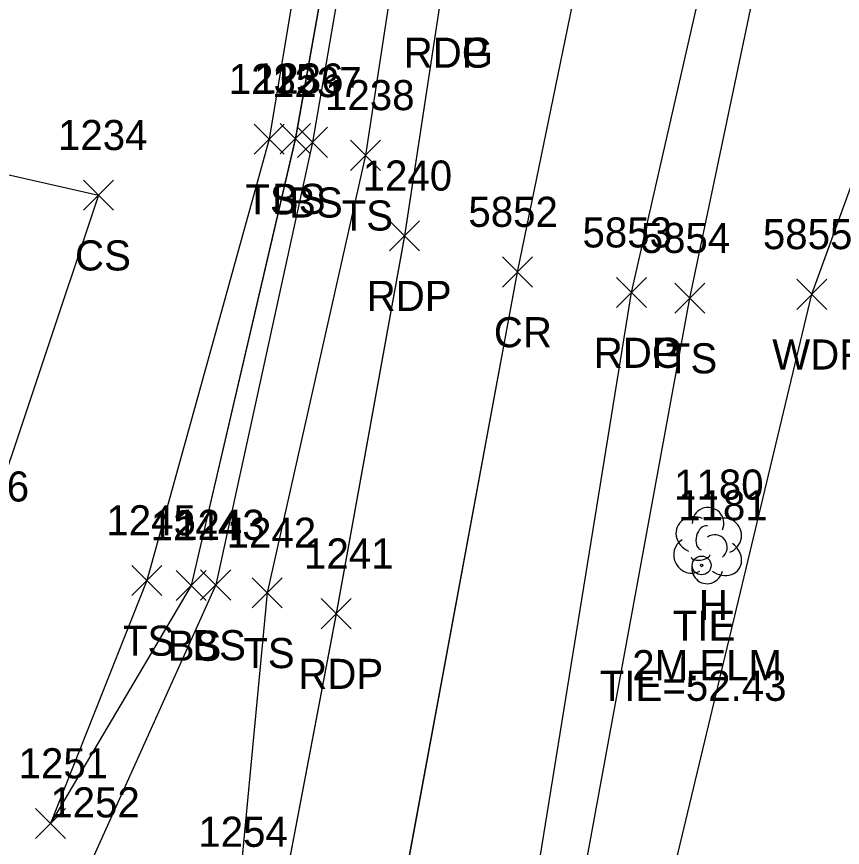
# Model space of a CAD drawing. Extents: x 1554668 to 1563881, y 831386 to 834374.
# Drawn here: x 1561833.7 to 1561888.6, y 833679 to 833734.2 of the extents above; entities that cross this region are included whole.
import ezdxf

# ---------------------------------------------------------------- set-up
doc = ezdxf.new("R2010")
doc.units = 0
for name, color, linetype in [('C_A', 7, 'Continuous'), ('C_C', 7, 'Continuous'), ('C_I', 7, 'Continuous'), ('CBP', 7, 'Continuous'), ('L_A', 7, 'Continuous'), ('L_C', 7, 'Continuous'), ('L_I', 7, 'Continuous'), ('L_TIC', 7, 'Continuous'), ('LAWA', 7, 'Continuous'), ('LELB', 7, 'Continuous'), ('LTD', 7, 'Continuous'), ('P_A', 7, 'Continuous'), ('P_I', 7, 'Continuous'), ('P_TIC', 7, 'Continuous'), ('PET', 7, 'Continuous'), ('PEU', 7, 'Continuous'), ('PRC', 7, 'Continuous')]:
    doc.layers.add(name, color=color, linetype=linetype)

msp = doc.modelspace()

# ---------------------------------------------------------------- linework, layer by layer
at = {"layer": 'CBP'}
for radius in [0.625, 0.0833]:
    msp.add_circle((1561879.207, 833697.748), radius, dxfattribs=at)
at = {"layer": 'L_TIC'}
for points in [[(1561849.467, 833725.074), (1561851.467, 833727.074)], [(1561851.467, 833725.074), (1561849.467, 833727.074)], [(1561851.199, 833725.106), (1561853.199, 833727.106)], [(1561853.199, 833725.106), (1561851.199, 833727.106)], [(1561852.344, 833724.866), (1561854.344, 833726.866)], [(1561854.344, 833724.866), (1561852.344, 833726.866)], [(1561855.867, 833724.001), (1561857.867, 833726.001)], [(1561857.867, 833724.001), (1561855.867, 833726.001)], [(1561838.114, 833721.348), (1561840.114, 833723.348)], [(1561840.114, 833721.348), (1561838.114, 833723.348)], [(1561877.419, 833714.511), (1561879.419, 833716.511)], [(1561879.419, 833714.511), (1561877.419, 833716.511)], [(1561885.539, 833714.765), (1561887.539, 833716.765)], [(1561887.539, 833714.765), (1561885.539, 833716.765)], [(1561841.33, 833695.748), (1561843.33, 833697.748)], [(1561843.33, 833695.748), (1561841.33, 833697.748)], [(1561844.274, 833695.41), (1561846.274, 833697.41)], [(1561846.274, 833695.41), (1561844.274, 833697.41)], [(1561845.906, 833695.447), (1561847.906, 833697.447)], [(1561847.906, 833695.447), (1561845.906, 833697.447)], [(1561849.329, 833694.923), (1561851.329, 833696.923)], [(1561851.329, 833694.923), (1561849.329, 833696.923)], [(1561834.929, 833679.601), (1561836.929, 833681.601)], [(1561836.929, 833679.601), (1561834.929, 833681.601)], [(1561834.929, 833679.601), (1561836.929, 833681.601)], [(1561836.929, 833679.601), (1561834.929, 833681.601)]]:
    msp.add_lwpolyline(points, dxfattribs=at)
at = {"layer": 'LAWA'}
for points in [[(1561868.017, 833554.593), (1561853.324, 833557.227), (1561862.973, 833614.369), (1561874.798, 833666.739), (1561886.539, 833715.765), (1561895.993, 833741.804), (1561893.776, 833756.696), (1561896.793, 833771.816), (1561900.446, 833801.465), (1561911.698, 833843.705), (1561917.941, 833890.876), (1561919.948, 833896.933), (1561931.794, 833916.188)], [(1561868.017, 833554.587), (1561853.326, 833557.225), (1561862.972, 833614.373), (1561874.796, 833666.738), (1561886.54, 833715.766), (1561895.995, 833741.807), (1561893.775, 833756.693), (1561896.794, 833771.816), (1561900.447, 833801.462), (1561911.703, 833843.707), (1561917.942, 833890.875), (1561919.949, 833896.931), (1561931.795, 833916.187)], [(1561868.017, 833554.587), (1561853.326, 833557.225), (1561862.972, 833614.373), (1561874.796, 833666.738), (1561886.54, 833715.766), (1561895.995, 833741.807), (1561893.775, 833756.693), (1561896.794, 833771.816), (1561900.447, 833801.462), (1561911.703, 833843.707), (1561917.942, 833890.875), (1561919.949, 833896.931), (1561931.795, 833916.187)], [(1561868.017, 833554.587), (1561853.326, 833557.225), (1561862.972, 833614.373), (1561874.796, 833666.738), (1561886.54, 833715.766), (1561895.995, 833741.807), (1561893.775, 833756.693), (1561896.794, 833771.816), (1561900.447, 833801.462), (1561911.703, 833843.707), (1561917.942, 833890.875), (1561919.949, 833896.931), (1561931.795, 833916.187)]]:
    msp.add_lwpolyline(points, dxfattribs=at)
at = {"layer": 'LELB'}
for points in [[(1561812.716, 833374.079), (1561818.656, 833401.248), (1561824.645, 833433.945), (1561832.252, 833470.48), (1561836.457, 833492.444), (1561840.257, 833509.466), (1561848.879, 833557.929), (1561859.972, 833614.877), (1561869.557, 833667.191), (1561878.418, 833715.509), (1561890.593, 833773.388), (1561895.718, 833803.087)], [(1561812.716, 833374.079), (1561818.656, 833401.248), (1561824.645, 833433.945), (1561832.252, 833470.48), (1561836.457, 833492.444), (1561840.257, 833509.466), (1561848.879, 833557.929), (1561859.972, 833614.877), (1561869.557, 833667.191), (1561878.418, 833715.509), (1561890.593, 833773.388), (1561895.718, 833803.087)], [(1561812.716, 833374.079), (1561818.656, 833401.248), (1561824.645, 833433.945), (1561832.252, 833470.48), (1561836.457, 833492.444), (1561840.257, 833509.466), (1561848.879, 833557.929), (1561859.972, 833614.877), (1561869.557, 833667.191), (1561878.418, 833715.509), (1561890.593, 833773.388), (1561895.718, 833803.087)], [(1561812.717, 833374.086), (1561818.657, 833401.257), (1561824.644, 833433.948), (1561832.251, 833470.485), (1561836.455, 833492.446), (1561840.257, 833509.472), (1561848.879, 833557.936), (1561859.973, 833614.873), (1561869.554, 833667.19), (1561878.419, 833715.511), (1561890.594, 833773.393), (1561895.717, 833803.083)], [(1561806.296, 833788.777), (1561837.712, 833773.958), (1561847.53, 833767.441), (1561857.265, 833760.518), (1561858.213, 833759.926), (1561859.161, 833759.715), (1561853.344, 833725.866), (1561846.906, 833696.447), (1561838.604, 833678.002)], [(1561806.297, 833788.773), (1561837.712, 833773.96), (1561847.53, 833767.436), (1561857.266, 833760.521), (1561858.213, 833759.923), (1561859.161, 833759.712), (1561853.344, 833725.864), (1561846.906, 833696.45), (1561838.605, 833677.998)], [(1561806.297, 833788.773), (1561837.712, 833773.96), (1561847.53, 833767.436), (1561857.266, 833760.521), (1561858.213, 833759.923), (1561859.161, 833759.712), (1561853.344, 833725.864), (1561846.906, 833696.45), (1561838.605, 833677.998)], [(1561806.297, 833788.773), (1561837.712, 833773.96), (1561847.53, 833767.436), (1561857.266, 833760.521), (1561858.213, 833759.923), (1561859.161, 833759.712), (1561853.344, 833725.864), (1561846.906, 833696.45), (1561838.605, 833677.998)], [(1561848.403, 833772.22), (1561859.088, 833762.967), (1561862.218, 833760.08), (1561856.867, 833725.001), (1561850.329, 833695.923), (1561848.444, 833676.048), (1561846.147, 833662.128), (1561840.876, 833636.676), (1561837.465, 833618.453), (1561834.406, 833616.246), (1561820.201, 833618.031), (1561806.977, 833621.804), (1561796.8, 833625.141), (1561796.213, 833627.925), (1561779.239, 833633.983)], [(1561848.403, 833772.219), (1561859.088, 833762.966), (1561862.218, 833760.077), (1561856.867, 833725.003), (1561850.329, 833695.921), (1561848.444, 833676.044), (1561846.147, 833662.13), (1561840.875, 833636.672), (1561837.466, 833618.455), (1561834.407, 833616.245), (1561820.203, 833618.032), (1561806.976, 833621.803), (1561796.804, 833625.143), (1561796.218, 833627.927), (1561779.24, 833633.983)], [(1561848.403, 833772.219), (1561859.088, 833762.966), (1561862.218, 833760.077), (1561856.867, 833725.003), (1561850.329, 833695.921), (1561848.444, 833676.044), (1561846.147, 833662.13), (1561840.875, 833636.672), (1561837.466, 833618.455), (1561834.407, 833616.245), (1561820.203, 833618.032), (1561806.976, 833621.803), (1561796.804, 833625.143), (1561796.218, 833627.927), (1561779.24, 833633.983)], [(1561848.403, 833772.219), (1561859.088, 833762.966), (1561862.218, 833760.077), (1561856.867, 833725.003), (1561850.329, 833695.921), (1561848.444, 833676.044), (1561846.147, 833662.13), (1561840.875, 833636.672), (1561837.466, 833618.455), (1561834.407, 833616.245), (1561820.203, 833618.032), (1561806.976, 833621.803), (1561796.804, 833625.143), (1561796.218, 833627.927), (1561779.24, 833633.983)], [(1561857.266, 833760.521), (1561853.903, 833746.709), (1561850.468, 833726.074), (1561842.33, 833696.752), (1561835.928, 833680.605)], [(1561857.266, 833760.521), (1561853.903, 833746.709), (1561850.468, 833726.074), (1561842.33, 833696.752), (1561835.928, 833680.605)], [(1561857.266, 833760.521), (1561853.903, 833746.709), (1561850.468, 833726.074), (1561842.33, 833696.752), (1561835.928, 833680.605)], [(1561857.265, 833760.518), (1561853.903, 833746.712), (1561850.467, 833726.074), (1561842.33, 833696.748), (1561835.929, 833680.601)], [(1561858.213, 833759.923), (1561852.2, 833726.109), (1561845.275, 833696.408), (1561835.928, 833680.605)], [(1561858.213, 833759.923), (1561852.2, 833726.109), (1561845.275, 833696.408), (1561835.928, 833680.605)], [(1561858.213, 833759.923), (1561852.2, 833726.109), (1561845.275, 833696.408), (1561835.928, 833680.605)], [(1561858.213, 833759.926), (1561852.199, 833726.106), (1561845.274, 833696.41), (1561835.929, 833680.601)], [(1561803.868, 833733.614), (1561825.939, 833725.332), (1561839.114, 833722.348), (1561831.301, 833698.995), (1561820.896, 833675.994)], [(1561803.87, 833733.611), (1561825.939, 833725.334), (1561839.115, 833722.351), (1561831.302, 833698.995), (1561820.898, 833675.993)], [(1561803.87, 833733.611), (1561825.939, 833725.334), (1561839.115, 833722.351), (1561831.302, 833698.995), (1561820.898, 833675.993)], [(1561803.87, 833733.611), (1561825.939, 833725.334), (1561839.115, 833722.351), (1561831.302, 833698.995), (1561820.898, 833675.993)]]:
    msp.add_lwpolyline(points, dxfattribs=at)
at = {"layer": 'LTD'}
msp.add_line((1561879.588, 833699.12), (1561879.588, 833699.12), dxfattribs=at)
msp.add_line((1561879.588, 833699.12), (1561879.588, 833699.12), dxfattribs=at)
msp.add_arc((1561879.635, 833700.554), 1.047, 335.5272, 180.9563, dxfattribs=at)
for centre, major_axis, ratio, start_param, end_param in [((1561878.797, 833699.786), (1.21, -0.512), 0.895232, 1.570796, 4.712389), ((1561880.63, 833699.703), (-1.141, -0.483), 0.949671, 1.570796, 4.712389), ((1561879.38, 833699.578), (-0.208, -0.792), 0.645439, 3.141593, 6.283185), ((1561878.505, 833698.411), (0.584, -1.042), 0.959034, 3.141593, 6.283185), ((1561880.088, 833698.953), (-0.5, 0.667), 0.989748, 3.141593, 6.283185), ((1561880.588, 833698.287), (-1.09, 0.792), 0.841452, 1.570796, 4.712389), ((1561879.13, 833698.37), (-0.625, -0.083), 0.423636, 0, 3.141593), ((1561879.589, 833697.62), (0.265, 1.061), 0.942809, 1.570796, 4.712389)]:
    msp.add_ellipse(centre, major_axis=major_axis, ratio=ratio, start_param=start_param, end_param=end_param, dxfattribs=at)
at = {"layer": 'P_TIC'}
for points in [[(1561858.453, 833718.656), (1561860.453, 833720.656)], [(1561860.453, 833718.656), (1561858.453, 833720.656)], [(1561865.962, 833716.246), (1561867.962, 833718.246)], [(1561867.962, 833716.246), (1561865.962, 833718.246)], [(1561873.547, 833714.877), (1561875.547, 833716.877)], [(1561875.547, 833714.877), (1561873.547, 833716.877)], [(1561873.547, 833714.877), (1561875.547, 833716.877)], [(1561875.547, 833714.877), (1561873.547, 833716.877)], [(1561853.907, 833693.541), (1561855.907, 833695.541)], [(1561855.907, 833693.541), (1561853.907, 833695.541)]]:
    msp.add_lwpolyline(points, dxfattribs=at)
at = {"layer": 'PET'}
for points in [[(1561861.913, 833735.821), (1561859.455, 833719.661), (1561854.908, 833694.543), (1561848.642, 833661.538), (1561838.871, 833614.304), (1561835.262, 833593.716), (1561828.939, 833559.501), (1561819.685, 833511.801), (1561817.414, 833499.273), (1561810.696, 833474.805), (1561802.99, 833435.764), (1561794.155, 833386.844), (1561787.73, 833353.76)], [(1561861.913, 833735.821), (1561859.455, 833719.661), (1561854.908, 833694.543), (1561848.642, 833661.538), (1561838.871, 833614.304), (1561835.262, 833593.716), (1561828.939, 833559.501), (1561819.685, 833511.801), (1561817.414, 833499.273), (1561810.696, 833474.805), (1561802.99, 833435.764), (1561794.155, 833386.844), (1561787.73, 833353.76)], [(1561861.913, 833735.821), (1561859.455, 833719.661), (1561854.908, 833694.543), (1561848.642, 833661.538), (1561838.871, 833614.304), (1561835.262, 833593.716), (1561828.939, 833559.501), (1561819.685, 833511.801), (1561817.414, 833499.273), (1561810.696, 833474.805), (1561802.99, 833435.764), (1561794.155, 833386.844), (1561787.73, 833353.76)], [(1561861.912, 833735.821), (1561859.453, 833719.656), (1561854.907, 833694.541), (1561848.644, 833661.541), (1561838.87, 833614.302), (1561835.26, 833593.712), (1561828.938, 833559.497), (1561819.684, 833511.802), (1561817.414, 833499.277), (1561810.694, 833474.801), (1561802.993, 833435.77), (1561794.153, 833386.847), (1561787.73, 833353.765)], [(1561809.846, 833376.005), (1561814.767, 833402.407), (1561821.298, 833434.706), (1561829.152, 833470.918), (1561832.475, 833490.835), (1561837.717, 833512.303), (1561846.35, 833556.717), (1561856.484, 833615.766), (1561866.775, 833667.81), (1561874.547, 833715.877)], [(1561809.846, 833376.001), (1561814.768, 833402.403), (1561821.3, 833434.703), (1561829.153, 833470.918), (1561832.475, 833490.828), (1561837.717, 833512.296), (1561846.35, 833556.707), (1561856.484, 833615.768), (1561866.773, 833667.809), (1561874.546, 833715.874)], [(1561809.846, 833376.001), (1561814.768, 833402.403), (1561821.3, 833434.703), (1561829.153, 833470.918), (1561832.475, 833490.828), (1561837.717, 833512.296), (1561846.35, 833556.707), (1561856.484, 833615.768), (1561866.773, 833667.809), (1561874.546, 833715.874)], [(1561809.846, 833376.001), (1561814.768, 833402.403), (1561821.3, 833434.703), (1561829.153, 833470.918), (1561832.475, 833490.828), (1561837.717, 833512.296), (1561846.35, 833556.707), (1561856.484, 833615.768), (1561866.773, 833667.809), (1561874.546, 833715.874)]]:
    msp.add_lwpolyline(points, dxfattribs=at)
at = {"layer": 'PEU'}
for points in [[(1561874.546, 833715.874), (1561887.478, 833772.584), (1561893.313, 833803.99), (1561901.362, 833845.453), (1561909.68, 833892.69), (1561910.734, 833900.622), (1561917.511, 833934.31), (1561919.487, 833947.442), (1561923.612, 833973.077), (1561931.593, 834020.004), (1561935.393, 834050.314), (1561943.165, 834094.381), (1561948.419, 834126.576), (1561953.285, 834146.878), (1561956.677, 834158.88)], [(1561874.546, 833715.874), (1561887.478, 833772.584), (1561893.313, 833803.99), (1561901.362, 833845.453), (1561909.68, 833892.69), (1561910.734, 833900.622), (1561917.511, 833934.31), (1561919.487, 833947.442), (1561923.612, 833973.077), (1561931.593, 834020.004), (1561935.393, 834050.314), (1561943.165, 834094.381), (1561948.419, 834126.576), (1561953.285, 834146.878), (1561956.677, 834158.88)], [(1561874.546, 833715.874), (1561887.478, 833772.584), (1561893.313, 833803.99), (1561901.362, 833845.453), (1561909.68, 833892.69), (1561910.734, 833900.622), (1561917.511, 833934.31), (1561919.487, 833947.442), (1561923.612, 833973.077), (1561931.593, 834020.004), (1561935.393, 834050.314), (1561943.165, 834094.381), (1561948.419, 834126.576), (1561953.285, 834146.878), (1561956.677, 834158.88)], [(1561874.547, 833715.877), (1561887.477, 833772.582), (1561893.312, 833803.991), (1561901.361, 833845.451), (1561909.679, 833892.687), (1561910.732, 833900.62), (1561917.51, 833934.306), (1561919.486, 833947.443), (1561923.61, 833973.073), (1561931.592, 834020.003), (1561935.394, 834050.314), (1561943.167, 834094.381), (1561948.417, 834126.574), (1561953.283, 834146.877), (1561956.677, 834158.88)]]:
    msp.add_lwpolyline(points, dxfattribs=at)
at = {"layer": 'PRC'}
for points in [[(1561800.21, 833371.538), (1561806.437, 833405.192), (1561812.654, 833434.931), (1561820.127, 833472.189), (1561827.528, 833505.749), (1561836.938, 833558.608), (1561848.037, 833617.29), (1561858.182, 833669.762), (1561866.962, 833717.246), (1561878.604, 833773.781), (1561885.024, 833806.831), (1561891.658, 833847.81), (1561899.783, 833893.72), (1561902.023, 833902.922), (1561908.115, 833944.075), (1561914.56, 833974.526), (1561922.248, 834021.375), (1561927.368, 834052.029), (1561935.214, 834095.998), (1561945.529, 834150.774)], [(1561800.212, 833371.537), (1561806.439, 833405.19), (1561812.656, 833434.927), (1561820.128, 833472.18), (1561827.529, 833505.744), (1561836.939, 833558.603), (1561848.037, 833617.288), (1561858.18, 833669.759), (1561866.961, 833717.243), (1561878.605, 833773.781), (1561885.024, 833806.829), (1561891.662, 833847.808), (1561899.784, 833893.716), (1561902.024, 833902.921), (1561908.116, 833944.071), (1561914.561, 833974.522), (1561922.249, 834021.372), (1561927.371, 834052.029), (1561935.212, 834095.998), (1561945.527, 834150.773)], [(1561800.212, 833371.537), (1561806.439, 833405.19), (1561812.656, 833434.927), (1561820.128, 833472.18), (1561827.529, 833505.744), (1561836.939, 833558.603), (1561848.037, 833617.288), (1561858.18, 833669.759), (1561866.961, 833717.243), (1561878.605, 833773.781), (1561885.024, 833806.829), (1561891.662, 833847.808), (1561899.784, 833893.716), (1561902.024, 833902.921), (1561908.116, 833944.071), (1561914.561, 833974.522), (1561922.249, 834021.372), (1561927.371, 834052.029), (1561935.212, 834095.998), (1561945.527, 834150.773)], [(1561800.212, 833371.537), (1561806.439, 833405.19), (1561812.656, 833434.927), (1561820.128, 833472.18), (1561827.529, 833505.744), (1561836.939, 833558.603), (1561848.037, 833617.288), (1561858.18, 833669.759), (1561866.961, 833717.243), (1561878.605, 833773.781), (1561885.024, 833806.829), (1561891.662, 833847.808), (1561899.784, 833893.716), (1561902.024, 833902.921), (1561908.116, 833944.071), (1561914.561, 833974.522), (1561922.249, 834021.372), (1561927.371, 834052.029), (1561935.212, 834095.998), (1561945.527, 834150.773)]]:
    msp.add_lwpolyline(points, dxfattribs=at)

# ---------------------------------------------------------------- texts
at = {"layer": 'C_A'}
msp.add_text('TIE', height=2, dxfattribs=at).set_placement((1561877.286, 833692.748))
at = {"layer": 'C_C'}
msp.add_text('TIE=52.43', height=2, dxfattribs=at).set_placement((1561872.436, 833688.748))
at = {"layer": 'C_I'}
msp.add_text('1181', height=2, dxfattribs=at).set_placement((1561877.648, 833700.748))
at = {"layer": 'L_A'}
for s, p in [('BS', (1561850.64, 833721.106)), ('TS', (1561848.877, 833721.074)), ('BS', (1561851.785, 833720.866)), ('TS', (1561855.276, 833720.001)), ('CS', (1561837.555, 833717.348)), ('WDR', (1561883.901, 833710.765)), ('TS', (1561876.828, 833710.511)), ('H', (1561879.021, 833694.12)), ('TS', (1561840.739, 833691.748)), ('BS', (1561843.715, 833691.41)), ('BS', (1561845.347, 833691.447)), ('TS', (1561848.738, 833690.923))]:
    msp.add_text(s, height=2, dxfattribs=at).set_placement(p)
at = {"layer": 'L_C'}
msp.add_text('2M.ELM', height=2, dxfattribs=at).set_placement((1561874.596, 833690.12))
at = {"layer": 'L_I'}
for s, p in [('1235', (1561847.774, 833729.074)), ('1236', (1561849.451, 833729.106)), ('1237', (1561850.651, 833728.866)), ('1238', (1561854.174, 833728.001)), ('1234', (1561836.421, 833725.348)), ('5854', (1561875.159, 833718.511)), ('5855', (1561883.279, 833718.765)), ('1246', (1561828.553, 833701.995)), ('1180', (1561877.376, 833702.12)), ('1245', (1561839.637, 833699.748)), ('1244', (1561842.581, 833699.41)), ('1243', (1561844.213, 833699.447)), ('1242', (1561847.636, 833698.923)), ('1251', (1561833.803, 833683.601)), ('1251', (1561833.803, 833683.601)), ('1252', (1561835.911, 833681.002)), ('1252', (1561835.911, 833681.002)), ('1254', (1561845.751, 833679.048)), ('1254', (1561845.751, 833679.048))]:
    msp.add_text(s, height=2, dxfattribs=at).set_placement(p)
at = {"layer": 'P_A'}
for s, p in [('RDG', (1561859.401, 833730.821)), ('RDP', (1561859.401, 833730.821)), ('RDP', (1561856.942, 833714.656)), ('CR', (1561865.395, 833712.246)), ('RDG', (1561872.035, 833710.877)), ('RDP', (1561872.035, 833710.877)), ('RDP', (1561852.395, 833689.541))]:
    msp.add_text(s, height=2, dxfattribs=at).set_placement(p)
at = {"layer": 'P_I'}
for s, p in [('1240', (1561856.674, 833722.656)), ('5852', (1561863.702, 833720.246)), ('5853', (1561871.287, 833718.877)), ('5853', (1561871.287, 833718.877)), ('1241', (1561852.781, 833697.541))]:
    msp.add_text(s, height=2, dxfattribs=at).set_placement(p)

doc.saveas('drawing.dxf')
